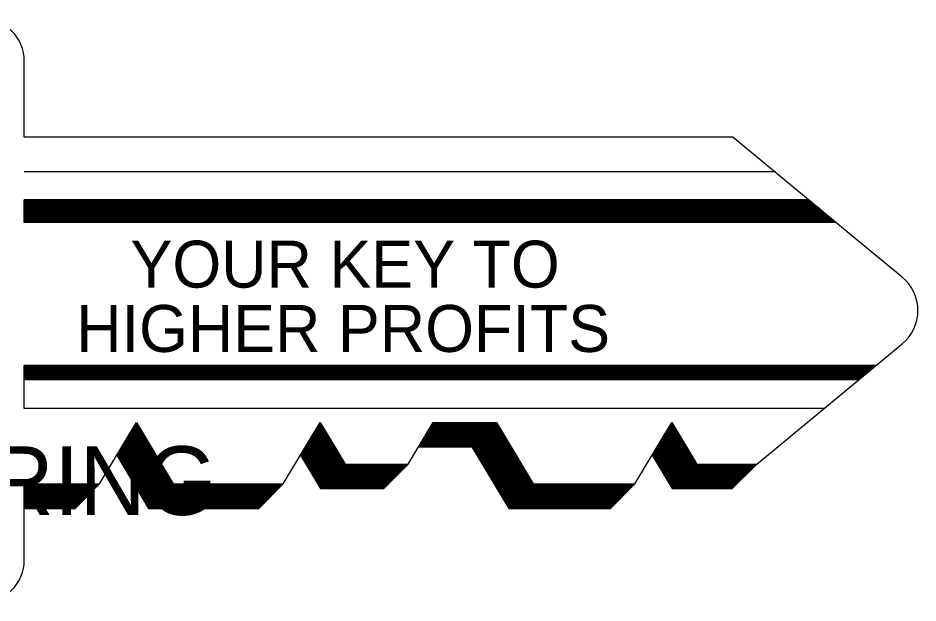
# Model space of a CAD drawing. Extents: x 0 to 53.3, y -0.3 to 37.1.
# Drawn here: x 4.481 to 6.21, y 1.867 to 2.992 of the extents above; entities that cross this region are included whole.
import ezdxf

# ---------------------------------------------------------------- set-up
doc = ezdxf.new("R2010")
doc.units = 0
doc.layers.add('Level 1', color=7, linetype='Continuous')

msp = doc.modelspace()

# ---------------------------------------------------------------- linework, layer by layer
at = {"layer": 'Level 1'}
for p, q in [((4.4932, 2.7624), (4.4932, 2.9083)), ((5.8546, 2.7624), (4.4932, 2.7624)), ((6.0521, 2.5991), (5.8549, 2.7624)), ((5.9352, 2.6958), (4.4932, 2.6958)), ((4.4932, 2.5986), (4.4932, 2.6421)), ((6.0001, 2.6421), (4.4932, 2.6421)), ((6.0014, 2.6411), (4.4932, 2.6411)), ((6.0026, 2.6401), (4.4932, 2.6401)), ((6.0039, 2.6389), (4.4932, 2.6389)), ((6.0054, 2.6378), (4.4932, 2.6378)), ((6.0067, 2.6366), (4.4932, 2.6366)), ((6.0084, 2.6353), (4.4932, 2.6353)), ((6.0097, 2.6341), (4.4932, 2.6341)), ((6.0114, 2.6328), (4.4932, 2.6328)), ((6.0131, 2.6314), (4.4932, 2.6314)), ((6.0144, 2.6303), (4.4932, 2.6303)), ((6.0159, 2.6289), (4.4932, 2.6289)), ((6.0156, 2.6293), (6.0151, 2.6298)), ((6.0164, 2.6286), (6.0156, 2.6293)), ((6.0177, 2.6276), (4.4932, 2.6276)), ((6.0191, 2.6264), (4.4932, 2.6264)), ((6.0204, 2.6253), (4.4932, 2.6253)), ((6.0221, 2.6239), (4.4932, 2.6239)), ((6.0237, 2.6226), (4.4932, 2.6226)), ((6.0252, 2.6213), (4.4932, 2.6213)), ((6.0271, 2.6198), (4.4932, 2.6198)), ((6.0286, 2.6186), (4.4932, 2.6186)), ((6.0301, 2.6173), (4.4932, 2.6173)), ((6.0319, 2.6158), (4.4932, 2.6158)), ((6.0336, 2.6144), (4.4932, 2.6144)), ((6.0347, 2.6134), (4.4932, 2.6134)), ((6.0364, 2.6121), (4.4932, 2.6121)), ((6.0216, 2.6243), (6.0164, 2.6286)), ((6.0239, 2.6224), (6.0216, 2.6243)), ((6.0379, 2.6108), (4.4932, 2.6108)), ((6.0394, 2.6096), (4.4932, 2.6096)), ((6.0407, 2.6084), (4.4932, 2.6084)), ((6.0421, 2.6074), (4.4932, 2.6074)), ((6.0439, 2.6059), (4.4932, 2.6059)), ((6.0451, 2.6049), (4.4932, 2.6049)), ((6.0464, 2.6038), (4.4932, 2.6038)), ((6.0476, 2.6028), (4.4932, 2.6028)), ((6.0489, 2.6018), (4.4932, 2.6018)), ((6.0499, 2.6009), (4.4932, 2.6009)), ((6.0511, 2.5999), (4.4932, 2.5999)), ((6.0519, 2.5993), (4.4932, 2.5993)), ((6.0527, 2.5986), (4.4932, 2.5986)), ((6.0527, 2.5986), (6.0521, 2.5991)), ((6.1802, 2.4933), (6.0527, 2.5986)), ((5.9006, 2.1338), (6.1802, 2.3649)), ((6.1299, 2.3233), (4.4932, 2.3233)), ((4.4932, 2.2406), (4.4932, 2.3233)), ((6.1272, 2.3211), (4.4932, 2.3211)), ((6.1244, 2.3188), (4.4932, 2.3188)), ((6.1212, 2.3161), (4.4932, 2.3161)), ((6.1186, 2.3139), (4.4932, 2.3139)), ((6.1154, 2.3113), (4.4932, 2.3113)), ((6.1126, 2.3089), (4.4932, 2.3089)), ((6.1096, 2.3064), (4.4932, 2.3064)), ((6.1062, 2.3038), (4.4932, 2.3038)), ((6.1032, 2.3013), (4.4932, 2.3013)), ((6.1004, 2.2989), (4.4932, 2.2989)), ((6.0984, 2.2973), (4.4932, 2.2973)), ((6.0966, 2.2958), (4.4932, 2.2958)), ((6.0299, 2.2406), (4.4932, 2.2406)), ((4.6377, 2.0958), (4.7086, 2.2139)), ((4.7086, 2.2139), (4.7792, 2.0958)), ((4.9909, 2.0958), (5.0616, 2.2139)), ((5.0616, 2.2139), (5.1097, 2.1338)), ((5.2311, 2.1338), (5.2791, 2.2139)), ((5.2791, 2.2139), (5.4004, 2.2139)), ((5.4004, 2.2139), (5.4712, 2.0958)), ((5.6666, 2.0958), (5.7374, 2.2139)), ((5.7374, 2.2139), (5.7854, 2.1338)), ((4.6987, 2.1976), (4.7184, 2.1976)), ((4.6996, 2.1989), (4.7176, 2.1989)), ((4.7004, 2.2003), (4.7167, 2.2003)), ((4.7012, 2.2016), (4.7159, 2.2016)), ((4.7019, 2.2029), (4.7151, 2.2029)), ((4.7027, 2.2043), (4.7144, 2.2043)), ((4.7036, 2.2056), (4.7136, 2.2056)), ((4.7044, 2.2069), (4.7127, 2.2069)), ((4.7052, 2.2083), (4.7119, 2.2083)), ((4.7059, 2.2096), (4.7112, 2.2096)), ((4.7067, 2.2109), (4.7104, 2.2109)), ((4.7076, 2.2123), (4.7096, 2.2123)), ((5.0517, 2.1976), (5.0714, 2.1976)), ((5.0526, 2.1989), (5.0706, 2.1989)), ((5.0534, 2.2003), (5.0697, 2.2003)), ((5.0542, 2.2016), (5.0689, 2.2016)), ((5.0549, 2.2029), (5.0681, 2.2029)), ((5.0557, 2.2043), (5.0674, 2.2043)), ((5.0566, 2.2056), (5.0666, 2.2056)), ((5.0574, 2.2069), (5.0657, 2.2069)), ((5.0582, 2.2083), (5.0649, 2.2083)), ((5.0589, 2.2096), (5.0642, 2.2096)), ((5.0596, 2.2106), (5.0636, 2.2106)), ((5.0602, 2.2116), (5.0629, 2.2116)), ((5.0607, 2.2126), (5.0624, 2.2126)), ((5.2692, 2.1976), (5.4102, 2.1976)), ((5.2701, 2.1989), (5.4094, 2.1989)), ((5.2709, 2.2003), (5.4086, 2.2003)), ((5.2717, 2.2016), (5.4077, 2.2016)), ((5.2724, 2.2029), (5.4069, 2.2029)), ((5.2732, 2.2043), (5.4062, 2.2043)), ((5.2741, 2.2056), (5.4054, 2.2056)), ((5.2749, 2.2069), (5.4046, 2.2069)), ((5.2757, 2.2083), (5.4037, 2.2083)), ((5.2764, 2.2094), (5.4031, 2.2094)), ((5.2771, 2.2106), (5.4024, 2.2106)), ((5.2777, 2.2118), (5.4017, 2.2118)), ((5.2784, 2.2128), (5.4011, 2.2128)), ((5.7276, 2.1976), (5.7472, 2.1976)), ((5.7284, 2.1989), (5.7464, 2.1989)), ((5.7292, 2.2003), (5.7456, 2.2003)), ((5.7301, 2.2016), (5.7447, 2.2016)), ((5.7307, 2.2029), (5.7439, 2.2029)), ((5.7316, 2.2043), (5.7432, 2.2043)), ((5.7324, 2.2056), (5.7424, 2.2056)), ((5.7332, 2.2069), (5.7416, 2.2069)), ((5.7341, 2.2083), (5.7407, 2.2083)), ((5.7347, 2.2096), (5.7401, 2.2096)), ((5.7354, 2.2106), (5.7394, 2.2106)), ((4.6884, 2.1803), (4.7287, 2.1803)), ((4.6892, 2.1816), (4.7279, 2.1816)), ((4.6901, 2.1829), (4.7271, 2.1829)), ((4.6907, 2.1843), (4.7262, 2.1843)), ((4.6916, 2.1856), (4.7256, 2.1856)), ((4.6924, 2.1869), (4.7247, 2.1869)), ((4.6932, 2.1883), (4.7239, 2.1883)), ((4.6941, 2.1896), (4.7231, 2.1896)), ((4.6949, 2.1909), (4.7224, 2.1909)), ((4.6957, 2.1923), (4.7216, 2.1923)), ((4.6966, 2.1936), (4.7207, 2.1936)), ((4.6974, 2.1949), (4.7199, 2.1949)), ((4.6979, 2.1963), (4.7191, 2.1963)), ((5.0414, 2.1803), (5.0817, 2.1803)), ((5.0422, 2.1816), (5.0809, 2.1816)), ((5.0431, 2.1829), (5.0801, 2.1829)), ((5.0437, 2.1843), (5.0792, 2.1843)), ((5.0446, 2.1856), (5.0786, 2.1856)), ((5.0454, 2.1869), (5.0777, 2.1869)), ((5.0462, 2.1883), (5.0769, 2.1883)), ((5.0471, 2.1896), (5.0761, 2.1896)), ((5.0479, 2.1909), (5.0754, 2.1909)), ((5.0487, 2.1923), (5.0746, 2.1923)), ((5.0496, 2.1936), (5.0737, 2.1936)), ((5.0504, 2.1949), (5.0729, 2.1949)), ((5.0509, 2.1963), (5.0721, 2.1963)), ((5.2589, 2.1803), (5.4206, 2.1803)), ((5.2597, 2.1816), (5.4197, 2.1816)), ((5.2606, 2.1829), (5.4189, 2.1829)), ((5.2612, 2.1843), (5.4181, 2.1843)), ((5.2621, 2.1856), (5.4174, 2.1856)), ((5.2629, 2.1869), (5.4166, 2.1869)), ((5.2637, 2.1883), (5.4157, 2.1883)), ((5.2646, 2.1896), (5.4149, 2.1896)), ((5.2652, 2.1909), (5.4142, 2.1909)), ((5.2661, 2.1923), (5.4134, 2.1923)), ((5.2669, 2.1936), (5.4126, 2.1936)), ((5.2677, 2.1949), (5.4117, 2.1949)), ((5.2686, 2.1963), (5.4109, 2.1963)), ((5.7172, 2.1803), (5.7576, 2.1803)), ((5.7181, 2.1816), (5.7567, 2.1816)), ((5.7189, 2.1829), (5.7559, 2.1829)), ((5.7196, 2.1843), (5.7551, 2.1843)), ((5.7204, 2.1856), (5.7544, 2.1856)), ((5.7212, 2.1869), (5.7536, 2.1869)), ((5.7221, 2.1883), (5.7527, 2.1883)), ((5.7229, 2.1896), (5.7519, 2.1896)), ((5.7237, 2.1909), (5.7512, 2.1909)), ((5.7246, 2.1923), (5.7504, 2.1923)), ((5.7254, 2.1936), (5.7496, 2.1936)), ((5.7262, 2.1949), (5.7487, 2.1949)), ((5.7267, 2.1963), (5.7479, 2.1963)), ((4.6781, 2.1629), (4.7391, 2.1629)), ((4.6789, 2.1643), (4.7382, 2.1643)), ((4.6797, 2.1656), (4.7374, 2.1656)), ((4.6806, 2.1669), (4.7367, 2.1669)), ((4.6814, 2.1683), (4.7359, 2.1683)), ((4.6822, 2.1696), (4.7351, 2.1696)), ((4.6831, 2.1709), (4.7342, 2.1709)), ((4.6839, 2.1723), (4.7336, 2.1723)), ((4.6844, 2.1736), (4.7327, 2.1736)), ((4.6852, 2.1749), (4.7319, 2.1749)), ((4.6861, 2.1763), (4.7311, 2.1763)), ((4.6867, 2.1776), (4.7302, 2.1776)), ((4.6876, 2.1789), (4.7296, 2.1789)), ((5.0311, 2.1629), (5.0921, 2.1629)), ((5.0319, 2.1643), (5.0912, 2.1643)), ((5.0327, 2.1656), (5.0904, 2.1656)), ((5.0336, 2.1669), (5.0897, 2.1669)), ((5.0344, 2.1683), (5.0889, 2.1683)), ((5.0352, 2.1696), (5.0881, 2.1696)), ((5.0361, 2.1709), (5.0872, 2.1709)), ((5.0369, 2.1723), (5.0866, 2.1723)), ((5.0374, 2.1736), (5.0857, 2.1736)), ((5.0382, 2.1749), (5.0849, 2.1749)), ((5.0391, 2.1763), (5.0841, 2.1763)), ((5.0397, 2.1776), (5.0832, 2.1776)), ((5.0406, 2.1789), (5.0826, 2.1789)), ((5.2509, 2.1669), (5.4286, 2.1669)), ((5.2509, 2.1668), (5.3532, 2.1668)), ((5.2517, 2.1683), (5.4277, 2.1683)), ((5.2526, 2.1696), (5.4269, 2.1696)), ((5.2534, 2.1709), (5.4261, 2.1709)), ((5.2541, 2.1723), (5.4254, 2.1723)), ((5.2549, 2.1736), (5.4246, 2.1736)), ((5.2557, 2.1749), (5.4237, 2.1749)), ((5.2566, 2.1763), (5.4229, 2.1763)), ((5.2572, 2.1776), (5.4221, 2.1776)), ((5.2581, 2.1789), (5.4214, 2.1789)), ((5.3532, 2.1668), (5.4241, 2.0486)), ((5.3539, 2.1656), (5.4292, 2.1656)), ((5.3547, 2.1643), (5.4301, 2.1643)), ((5.3556, 2.1629), (5.4309, 2.1629)), ((5.7069, 2.1629), (5.7679, 2.1629)), ((5.7077, 2.1643), (5.7671, 2.1643)), ((5.7086, 2.1656), (5.7662, 2.1656)), ((5.7094, 2.1669), (5.7656, 2.1669)), ((5.7102, 2.1683), (5.7647, 2.1683)), ((5.7111, 2.1696), (5.7639, 2.1696)), ((5.7119, 2.1709), (5.7631, 2.1709)), ((5.7127, 2.1723), (5.7624, 2.1723)), ((5.7132, 2.1736), (5.7616, 2.1736)), ((5.7141, 2.1749), (5.7607, 2.1749)), ((5.7149, 2.1763), (5.7599, 2.1763)), ((5.7156, 2.1776), (5.7591, 2.1776)), ((5.7164, 2.1789), (5.7584, 2.1789)), ((4.6709, 2.1509), (4.7321, 2.0486)), ((4.6709, 2.1509), (4.7462, 2.1509)), ((4.6716, 2.1523), (4.7454, 2.1523)), ((4.6717, 2.1496), (4.7471, 2.1496)), ((4.6724, 2.1536), (4.7446, 2.1536)), ((4.6726, 2.1483), (4.7479, 2.1483)), ((4.6732, 2.1549), (4.7439, 2.1549)), ((4.6732, 2.1469), (4.7486, 2.1469)), ((4.6741, 2.1563), (4.7431, 2.1563)), ((4.6741, 2.1456), (4.7494, 2.1456)), ((4.6747, 2.1576), (4.7422, 2.1576)), ((4.6756, 2.1589), (4.7414, 2.1589)), ((4.6764, 2.1603), (4.7407, 2.1603)), ((4.6772, 2.1616), (4.7399, 2.1616)), ((5.0239, 2.1509), (5.0626, 2.0866)), ((5.0239, 2.1509), (5.0992, 2.1509)), ((5.0246, 2.1523), (5.0984, 2.1523)), ((5.0247, 2.1496), (5.1001, 2.1496)), ((5.0254, 2.1536), (5.0976, 2.1536)), ((5.0256, 2.1483), (5.1009, 2.1483)), ((5.0262, 2.1549), (5.0969, 2.1549)), ((5.0262, 2.1469), (5.1016, 2.1469)), ((5.0271, 2.1563), (5.0961, 2.1563)), ((5.0271, 2.1456), (5.1024, 2.1456)), ((5.0277, 2.1576), (5.0952, 2.1576)), ((5.0286, 2.1589), (5.0944, 2.1589)), ((5.0294, 2.1603), (5.0937, 2.1603)), ((5.0302, 2.1616), (5.0929, 2.1616)), ((5.3564, 2.1616), (5.4317, 2.1616)), ((5.3571, 2.1603), (5.4326, 2.1603)), ((5.3579, 2.1589), (5.4332, 2.1589)), ((5.3587, 2.1576), (5.4341, 2.1576)), ((5.3596, 2.1563), (5.4349, 2.1563)), ((5.3604, 2.1549), (5.4357, 2.1549)), ((5.3611, 2.1536), (5.4364, 2.1536)), ((5.3619, 2.1523), (5.4372, 2.1523)), ((5.3627, 2.1509), (5.4381, 2.1509)), ((5.3636, 2.1496), (5.4389, 2.1496)), ((5.3644, 2.1483), (5.4397, 2.1483)), ((5.3651, 2.1469), (5.4404, 2.1469)), ((5.3659, 2.1456), (5.4412, 2.1456)), ((5.6997, 2.1509), (5.7382, 2.0866)), ((5.6997, 2.1509), (5.7751, 2.1509)), ((5.7004, 2.1523), (5.7742, 2.1523)), ((5.7006, 2.1496), (5.7759, 2.1496)), ((5.7012, 2.1536), (5.7734, 2.1536)), ((5.7014, 2.1483), (5.7767, 2.1483)), ((5.7021, 2.1549), (5.7727, 2.1549)), ((5.7021, 2.1469), (5.7774, 2.1469)), ((5.7029, 2.1563), (5.7719, 2.1563)), ((5.7029, 2.1456), (5.7782, 2.1456)), ((5.7036, 2.1576), (5.7711, 2.1576)), ((5.7044, 2.1589), (5.7702, 2.1589)), ((5.7052, 2.1603), (5.7696, 2.1603)), ((5.7061, 2.1616), (5.7687, 2.1616)), ((4.6749, 2.1443), (4.7499, 2.1443)), ((4.6757, 2.1429), (4.7507, 2.1429)), ((4.6764, 2.1416), (4.7516, 2.1416)), ((4.6772, 2.1403), (4.7524, 2.1403)), ((4.6781, 2.1389), (4.7532, 2.1389)), ((4.6789, 2.1376), (4.7541, 2.1376)), ((4.6797, 2.1363), (4.7549, 2.1363)), ((4.6804, 2.1349), (4.7557, 2.1349)), ((4.6812, 2.1336), (4.7566, 2.1336)), ((4.6821, 2.1323), (4.7574, 2.1323)), ((4.6827, 2.1313), (4.7581, 2.1313)), ((4.6834, 2.1299), (4.7587, 2.1299)), ((4.6842, 2.1286), (4.7596, 2.1286)), ((5.0279, 2.1443), (5.1029, 2.1443)), ((5.0287, 2.1429), (5.1037, 2.1429)), ((5.0294, 2.1416), (5.1046, 2.1416)), ((5.0302, 2.1403), (5.1054, 2.1403)), ((5.0311, 2.1389), (5.1062, 2.1389)), ((5.0319, 2.1376), (5.1071, 2.1376)), ((5.0327, 2.1363), (5.1079, 2.1363)), ((5.0334, 2.1349), (5.1087, 2.1349)), ((5.0342, 2.1336), (5.1096, 2.1336)), ((5.0351, 2.1323), (5.1104, 2.1323)), ((5.0357, 2.1313), (5.1111, 2.1313)), ((5.0364, 2.1299), (5.1117, 2.1299)), ((5.0372, 2.1286), (5.1126, 2.1286)), ((5.0866, 2.1321), (5.2294, 2.1321)), ((5.0866, 2.1306), (5.2279, 2.1306)), ((5.0866, 2.1291), (5.2264, 2.1291)), ((5.0866, 2.1273), (5.2246, 2.1273)), ((5.1097, 2.1338), (5.2311, 2.1338)), ((5.1839, 2.0866), (5.2311, 2.1338)), ((5.3667, 2.1443), (5.4417, 2.1443)), ((5.3676, 2.1429), (5.4426, 2.1429)), ((5.3682, 2.1416), (5.4434, 2.1416)), ((5.3691, 2.1403), (5.4442, 2.1403)), ((5.3699, 2.1389), (5.4451, 2.1389)), ((5.3707, 2.1376), (5.4459, 2.1376)), ((5.3716, 2.1363), (5.4467, 2.1363)), ((5.3722, 2.1349), (5.4476, 2.1349)), ((5.3731, 2.1336), (5.4484, 2.1336)), ((5.3739, 2.1323), (5.4492, 2.1323)), ((5.3746, 2.1313), (5.4499, 2.1313)), ((5.3752, 2.1299), (5.4506, 2.1299)), ((5.3761, 2.1286), (5.4514, 2.1286)), ((5.7037, 2.1443), (5.7787, 2.1443)), ((5.7046, 2.1429), (5.7796, 2.1429)), ((5.7052, 2.1416), (5.7804, 2.1416)), ((5.7061, 2.1403), (5.7812, 2.1403)), ((5.7069, 2.1389), (5.7821, 2.1389)), ((5.7077, 2.1376), (5.7829, 2.1376)), ((5.7086, 2.1363), (5.7837, 2.1363)), ((5.7092, 2.1349), (5.7846, 2.1349)), ((5.7101, 2.1336), (5.7854, 2.1336)), ((5.7109, 2.1323), (5.7862, 2.1323)), ((5.7116, 2.1313), (5.7869, 2.1313)), ((5.7122, 2.1299), (5.7876, 2.1299)), ((5.7131, 2.1286), (5.7884, 2.1286)), ((5.7624, 2.1321), (5.8989, 2.1321)), ((5.7624, 2.1306), (5.8974, 2.1306)), ((5.7624, 2.1291), (5.8959, 2.1291)), ((5.7624, 2.1273), (5.8941, 2.1273)), ((5.7854, 2.1338), (5.9006, 2.1338)), ((5.8534, 2.0866), (5.9006, 2.1338)), ((4.6851, 2.1271), (4.7606, 2.1271)), ((4.6861, 2.1254), (4.7616, 2.1254)), ((4.6871, 2.1239), (4.7624, 2.1239)), ((4.6881, 2.1221), (4.7636, 2.1221)), ((4.6891, 2.1204), (4.7644, 2.1204)), ((4.6904, 2.1184), (4.7657, 2.1184)), ((4.6914, 2.1166), (4.7667, 2.1166)), ((4.6926, 2.1146), (4.7679, 2.1146)), ((4.6937, 2.1126), (4.7692, 2.1126)), ((4.6947, 2.1109), (4.7702, 2.1109)), ((5.0381, 2.1271), (5.1136, 2.1271)), ((5.0391, 2.1254), (5.1146, 2.1254)), ((5.0401, 2.1239), (5.1154, 2.1239)), ((5.0406, 2.1233), (5.2206, 2.1233)), ((5.0417, 2.1213), (5.2186, 2.1213)), ((5.0429, 2.1193), (5.2166, 2.1193)), ((5.0441, 2.1174), (5.2147, 2.1174)), ((5.0452, 2.1154), (5.2127, 2.1154)), ((5.0464, 2.1134), (5.2107, 2.1134)), ((5.0476, 2.1114), (5.2087, 2.1114)), ((5.0866, 2.1254), (5.2227, 2.1254)), ((5.3769, 2.1271), (5.4524, 2.1271)), ((5.3779, 2.1254), (5.4534, 2.1254)), ((5.3789, 2.1239), (5.4542, 2.1239)), ((5.3799, 2.1221), (5.4554, 2.1221)), ((5.3809, 2.1204), (5.4562, 2.1204)), ((5.3822, 2.1184), (5.4576, 2.1184)), ((5.3832, 2.1166), (5.4586, 2.1166)), ((5.3844, 2.1146), (5.4597, 2.1146)), ((5.3856, 2.1126), (5.4611, 2.1126)), ((5.3866, 2.1109), (5.4621, 2.1109)), ((5.7139, 2.1271), (5.7894, 2.1271)), ((5.7149, 2.1254), (5.7904, 2.1254)), ((5.7159, 2.1239), (5.7912, 2.1239)), ((5.7164, 2.1233), (5.8901, 2.1233)), ((5.7176, 2.1213), (5.8881, 2.1213)), ((5.7187, 2.1193), (5.8861, 2.1193)), ((5.7199, 2.1174), (5.8842, 2.1174)), ((5.7211, 2.1154), (5.8822, 2.1154)), ((5.7222, 2.1134), (5.8802, 2.1134)), ((5.7234, 2.1114), (5.8782, 2.1114)), ((5.7624, 2.1254), (5.8922, 2.1254)), ((4.4932, 1.9499), (4.4932, 2.0958)), ((4.4932, 2.0958), (4.6377, 2.0958)), ((4.4932, 2.0941), (4.6361, 2.0941)), ((4.4932, 2.0926), (4.6346, 2.0926)), ((4.5906, 2.0486), (4.6377, 2.0958)), ((4.6957, 2.1093), (4.7712, 2.1093)), ((4.6971, 2.1073), (4.7724, 2.1073)), ((4.6981, 2.1054), (4.7734, 2.1054)), ((4.6992, 2.1034), (4.7746, 2.1034)), ((4.7009, 2.1008), (4.7762, 2.1008)), ((4.7022, 2.0986), (4.7776, 2.0986)), ((4.7036, 2.0963), (4.7789, 2.0963)), ((4.7049, 2.0941), (4.9892, 2.0941)), ((4.7057, 2.0926), (4.9877, 2.0926)), ((4.7792, 2.0958), (4.9909, 2.0958)), ((4.9437, 2.0486), (4.9909, 2.0958)), ((5.0489, 2.1094), (5.2067, 2.1094)), ((5.0496, 2.1081), (5.2054, 2.1081)), ((5.0506, 2.1066), (5.2039, 2.1066)), ((5.0517, 2.1046), (5.2019, 2.1046)), ((5.0529, 2.1026), (5.1999, 2.1026)), ((5.0539, 2.1009), (5.1982, 2.1009)), ((5.0552, 2.0988), (5.1961, 2.0988)), ((5.0564, 2.0968), (5.1941, 2.0968)), ((5.0577, 2.0948), (5.1921, 2.0948)), ((5.0587, 2.0929), (5.1902, 2.0929)), ((5.3876, 2.1093), (5.4631, 2.1093)), ((5.3889, 2.1073), (5.4642, 2.1073)), ((5.3899, 2.1054), (5.4652, 2.1054)), ((5.3911, 2.1034), (5.4664, 2.1034)), ((5.3927, 2.1008), (5.4681, 2.1008)), ((5.3941, 2.0986), (5.4694, 2.0986)), ((5.3954, 2.0963), (5.4707, 2.0963)), ((5.3967, 2.0941), (5.6649, 2.0941)), ((5.3976, 2.0926), (5.6634, 2.0926)), ((5.4712, 2.0958), (5.6666, 2.0958)), ((5.6194, 2.0486), (5.6666, 2.0958)), ((5.7247, 2.1094), (5.8762, 2.1094)), ((5.7254, 2.1081), (5.8749, 2.1081)), ((5.7264, 2.1066), (5.8734, 2.1066)), ((5.7276, 2.1046), (5.8714, 2.1046)), ((5.7287, 2.1026), (5.8694, 2.1026)), ((5.7297, 2.1009), (5.8677, 2.1009)), ((5.7311, 2.0988), (5.8656, 2.0988)), ((5.7322, 2.0968), (5.8636, 2.0968)), ((5.7336, 2.0948), (5.8616, 2.0948)), ((5.7346, 2.0929), (5.8597, 2.0929)), ((4.4932, 2.0911), (4.6331, 2.0911)), ((4.4932, 2.0893), (4.6312, 2.0893)), ((4.4932, 2.0874), (4.6294, 2.0874)), ((4.4932, 2.0853), (4.6272, 2.0853)), ((4.4932, 2.0833), (4.6252, 2.0833)), ((4.4932, 2.0813), (4.6232, 2.0813)), ((4.4932, 2.0794), (4.6214, 2.0794)), ((4.4932, 2.0774), (4.6194, 2.0774)), ((4.4932, 2.0754), (4.6174, 2.0754)), ((4.7067, 2.0911), (4.9862, 2.0911)), ((4.7077, 2.0893), (4.9844, 2.0893)), ((4.7089, 2.0874), (4.9826, 2.0874)), ((4.7102, 2.0853), (4.9804, 2.0853)), ((4.7114, 2.0833), (4.9784, 2.0833)), ((4.7126, 2.0813), (4.9764, 2.0813)), ((4.7136, 2.0794), (4.9746, 2.0794)), ((4.7149, 2.0774), (4.9726, 2.0774)), ((4.7161, 2.0754), (4.9706, 2.0754)), ((5.0602, 2.0906), (5.1879, 2.0906)), ((5.0614, 2.0886), (5.1859, 2.0886)), ((5.0626, 2.0866), (5.1839, 2.0866)), ((5.3986, 2.0911), (5.6619, 2.0911)), ((5.3996, 2.0893), (5.6601, 2.0893)), ((5.4007, 2.0874), (5.6582, 2.0874)), ((5.4021, 2.0853), (5.6561, 2.0853)), ((5.4032, 2.0833), (5.6541, 2.0833)), ((5.4044, 2.0813), (5.6521, 2.0813)), ((5.4054, 2.0794), (5.6502, 2.0794)), ((5.4067, 2.0774), (5.6482, 2.0774)), ((5.4079, 2.0754), (5.6462, 2.0754)), ((5.7361, 2.0906), (5.8574, 2.0906)), ((5.7372, 2.0886), (5.8554, 2.0886)), ((5.7382, 2.0866), (5.8534, 2.0866)), ((4.4932, 2.0734), (4.6154, 2.0734)), ((4.4932, 2.0714), (4.6134, 2.0714)), ((4.4932, 2.0701), (4.6121, 2.0701)), ((4.4932, 2.0686), (4.6106, 2.0686)), ((4.4932, 2.0666), (4.6086, 2.0666)), ((4.4932, 2.0646), (4.6066, 2.0646)), ((4.4932, 2.0629), (4.6049, 2.0629)), ((4.4932, 2.0608), (4.6027, 2.0608)), ((4.4932, 2.0588), (4.6007, 2.0588)), ((4.7172, 2.0734), (4.9686, 2.0734)), ((4.7184, 2.0714), (4.9666, 2.0714)), ((4.7192, 2.0701), (4.9652, 2.0701)), ((4.7201, 2.0686), (4.9637, 2.0686)), ((4.7212, 2.0666), (4.9617, 2.0666)), ((4.7226, 2.0646), (4.9597, 2.0646)), ((4.7236, 2.0629), (4.9581, 2.0629)), ((4.7247, 2.0608), (4.9559, 2.0608)), ((4.7261, 2.0588), (4.9539, 2.0588)), ((5.4091, 2.0734), (5.6442, 2.0734)), ((5.4102, 2.0714), (5.6422, 2.0714)), ((5.4111, 2.0701), (5.6409, 2.0701)), ((5.4119, 2.0686), (5.6394, 2.0686)), ((5.4131, 2.0666), (5.6374, 2.0666)), ((5.4144, 2.0646), (5.6354, 2.0646)), ((5.4154, 2.0629), (5.6337, 2.0629)), ((5.4166, 2.0608), (5.6316, 2.0608)), ((5.4179, 2.0588), (5.6296, 2.0588)), ((4.4932, 2.0568), (4.5987, 2.0568)), ((4.4932, 2.0549), (4.5969, 2.0549)), ((4.4932, 2.0526), (4.5946, 2.0526)), ((4.4932, 2.0506), (4.5926, 2.0506)), ((4.4932, 2.0486), (4.5906, 2.0486)), ((4.7272, 2.0568), (4.9519, 2.0568)), ((4.7282, 2.0549), (4.9501, 2.0549)), ((4.7297, 2.0526), (4.9477, 2.0526)), ((4.7309, 2.0506), (4.9457, 2.0506)), ((4.7321, 2.0486), (4.9437, 2.0486)), ((5.4191, 2.0568), (5.6276, 2.0568)), ((5.4201, 2.0549), (5.6257, 2.0549)), ((5.4216, 2.0526), (5.6234, 2.0526)), ((5.4227, 2.0506), (5.6214, 2.0506)), ((5.4241, 2.0486), (5.6194, 2.0486))]:
    msp.add_line(p, q, dxfattribs=at)
for centre, start, end in [((4.4099, 2.9083), 0, 90), ((6.1271, 2.4291), 309.5794, 50.3991), ((4.4099, 1.9499), 270, 0)]:
    msp.add_arc(centre, 0.0833, start, end, dxfattribs=at)

# ---------------------------------------------------------------- texts
for s, height, p in [('YOUR KEY TO', 0.090249, (4.6972, 2.4731)), ('HIGHER PROFITS', 0.090249, (4.5929, 2.3494)), ('ENGINEERING', 0.13199, (3.6281, 2.0359))]:
    msp.add_text(s, height=height, dxfattribs=at).set_placement(p)

doc.saveas('drawing.dxf')
